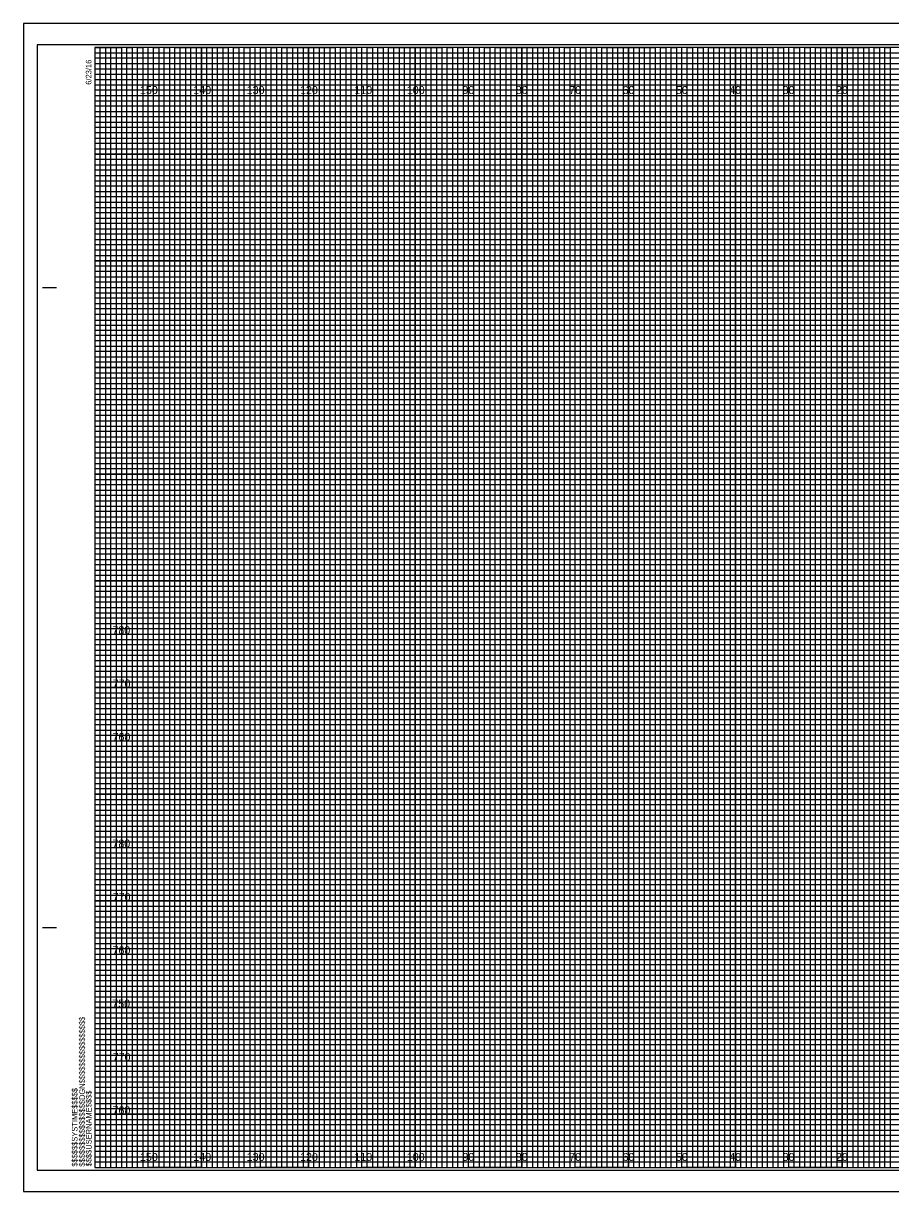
# Model space of a CAD drawing. Extents: x -13 to 323, y -4 to 214.
# Drawn here: x -13.4 to 149.1, y -4.5 to 214.5 of the extents above; entities that cross this region are included whole.
import ezdxf

# ---------------------------------------------------------------- set-up
doc = ezdxf.new("R2010")
doc.units = 0
for name, color, linetype in [('Exist Cross Section Cell', 7, 'Continuous'), ('Exist XS Center Line Elevation Label', 7, 'Continuous'), ('Exist XS Ground Line', 7, 'Continuous'), ('Prop CMT Pvmt Course 2', 7, 'Continuous'), ('Prop CMT Pvmt Course 3', 7, 'Continuous'), ('Prop CMT Pvmt Surface', 7, 'Continuous'), ('Prop CMT Shld Paved Course 1', 7, 'Continuous'), ('Prop CMT Shld Paved Course 3', 7, 'Continuous'), ('Prop CMT Subgrade Earthwork', 7, 'Continuous'), ('Scratch_Level_1', 7, 'Continuous'), ('Scratch_Level_7', 7, 'Continuous')]:
    doc.layers.add(name, color=color, linetype=linetype)

msp = doc.modelspace()

# ---------------------------------------------------------------- linework, layer by layer
at = {"layer": 'Exist XS Center Line Elevation Label'}
for points in [[(0, 210), (5, 210), (5, 0), (15, 0), (15, 210), (25, 210), (25, 0), (35, 0), (35, 210), (45, 210), (45, 0), (55, 0), (55, 210), (65, 210), (65, 0), (75, 0), (75, 210), (85, 210), (85, 0), (95, 0), (95, 210), (105, 210), (105, 0), (115, 0), (115, 210), (125, 210), (125, 0), (135, 0), (135, 210), (145, 210), (145, 0), (155, 0)], [(0, 205), (275, 205)], [(0, 185), (320, 185), (320, 195), (0, 195)], [(0, 165), (320, 165), (320, 175), (0, 175)], [(0, 145), (320, 145), (320, 155), (0, 155)], [(0, 125), (320, 125), (320, 135), (0, 135)], [(0, 105), (320, 105), (320, 115), (0, 115)], [(0, 85), (320, 85), (320, 95), (0, 95)], [(0, 65), (320, 65), (320, 75), (0, 75)], [(0, 45), (320, 45), (320, 55), (0, 55)], [(0, 25), (320, 25), (320, 35), (0, 35)], [(0, 5), (320, 5), (320, 15), (0, 15)]]:
    msp.add_lwpolyline(points, dxfattribs=at)
at = {"layer": 'Exist XS Ground Line'}
for p, q in [((10, 210), (0, 210)), ((10, 0), (10, 210)), ((30, 210), (20, 210)), ((20, 210), (20, 0)), ((30, 0), (30, 210)), ((50, 210), (40, 210)), ((40, 210), (40, 0)), ((50, 0), (50, 210)), ((70, 210), (60, 210)), ((60, 210), (60, 0)), ((70, 0), (70, 210)), ((90, 210), (80, 210)), ((80, 210), (80, 0)), ((90, 0), (90, 210)), ((110, 210), (100, 210)), ((100, 210), (100, 0)), ((110, 0), (110, 210)), ((130, 210), (120, 210)), ((120, 210), (120, 0)), ((130, 0), (130, 210)), ((150, 210), (140, 210)), ((140, 210), (140, 0)), ((20, 0), (10, 0)), ((40, 0), (30, 0)), ((60, 0), (50, 0)), ((80, 0), (70, 0)), ((100, 0), (90, 0)), ((120, 0), (110, 0)), ((140, 0), (130, 0))]:
    msp.add_line(p, q, dxfattribs=at)
for points in [[(0, 200), (320, 200), (320, 190), (0, 190)], [(0, 180), (320, 180), (320, 170), (0, 170)], [(0, 160), (320, 160), (320, 150), (0, 150)], [(0, 140), (320, 140), (320, 130), (0, 130)], [(0, 120), (320, 120), (320, 110), (0, 110)], [(0, 100), (320, 100), (320, 90), (0, 90)], [(0, 80), (320, 80), (320, 70), (0, 70)], [(0, 60), (320, 60), (320, 50), (0, 50)], [(0, 40), (320, 40), (320, 30), (0, 30)], [(0, 20), (320, 20), (320, 10), (0, 10)]]:
    msp.add_lwpolyline(points, dxfattribs=at)
at = {"layer": 'Prop CMT Pvmt Course 2'}
msp.add_lwpolyline([(-10.8, -0.5), (322.4, -0.5), (322.4, 210.5), (-10.8, 210.5)], close=True, dxfattribs=at)
at = {"layer": 'Prop CMT Pvmt Course 3'}
for p, q in [((10, 0), (10, 210)), ((20, 0), (20, 210)), ((30, 0), (30, 210)), ((40, 0), (40, 210)), ((50, 0), (50, 210)), ((60, 0), (60, 210)), ((70, 0), (70, 210)), ((80, 0), (80, 210)), ((90, 0), (90, 210)), ((100, 0), (100, 210)), ((110, 0), (110, 210)), ((120, 0), (120, 210)), ((130, 0), (130, 210)), ((140, 0), (140, 210)), ((0, 200), (320, 200)), ((0, 190), (320, 190)), ((0, 180), (320, 180)), ((0, 170), (320, 170)), ((0, 160), (320, 160)), ((0, 150), (320, 150)), ((0, 140), (320, 140)), ((0, 130), (320, 130)), ((0, 120), (320, 120)), ((0, 110), (320, 110)), ((0, 100), (320, 100)), ((0, 90), (320, 90)), ((0, 80), (320, 80)), ((0, 70), (320, 70)), ((0, 60), (320, 60)), ((0, 50), (320, 50)), ((0, 40), (320, 40)), ((0, 30), (320, 30)), ((0, 20), (320, 20)), ((0, 10), (320, 10))]:
    msp.add_line(p, q, dxfattribs=at)
at = {"layer": 'Prop CMT Shld Paved Course 1'}
for points in [[(0, 0), (1, 0), (1, 210), (2, 210), (2, 0)], [(2, 0), (3, 0), (3, 210), (4, 210), (4, 0)], [(5, 0), (6, 0), (6, 210), (7, 210), (7, 0)], [(7, 0), (8, 0), (8, 210), (9, 210), (9, 0)], [(10, 0), (11, 0), (11, 210), (12, 210), (12, 0)], [(12, 0), (13, 0), (13, 210), (14, 210), (14, 0)], [(15, 0), (16, 0), (16, 210), (17, 210), (17, 0)], [(17, 0), (18, 0), (18, 210), (19, 210), (19, 0)], [(20, 0), (21, 0), (21, 210), (22, 210), (22, 0)], [(22, 0), (23, 0), (23, 210), (24, 210), (24, 0)], [(25, 0), (26, 0), (26, 210), (27, 210), (27, 0)], [(27, 0), (28, 0), (28, 210), (29, 210), (29, 0)], [(30, 0), (31, 0), (31, 210), (32, 210), (32, 0)], [(32, 0), (33, 0), (33, 210), (34, 210), (34, 0)], [(35, 0), (36, 0), (36, 210), (37, 210), (37, 0)], [(37, 0), (38, 0), (38, 210), (39, 210), (39, 0)], [(40, 0), (41, 0), (41, 210), (42, 210), (42, 0)], [(42, 0), (43, 0), (43, 210), (44, 210), (44, 0)], [(45, 0), (46, 0), (46, 210), (47, 210), (47, 0)], [(47, 0), (48, 0), (48, 210), (49, 210), (49, 0)], [(50, 0), (51, 0), (51, 210), (52, 210), (52, 0)], [(52, 0), (53, 0), (53, 210), (54, 210), (54, 0)], [(55, 0), (56, 0), (56, 210), (57, 210), (57, 0)], [(57, 0), (58, 0), (58, 210), (59, 210), (59, 0)], [(60, 0), (61, 0), (61, 210), (62, 210), (62, 0)], [(62, 0), (63, 0), (63, 210), (64, 210), (64, 0)], [(65, 0), (66, 0), (66, 210), (67, 210), (67, 0)], [(67, 0), (68, 0), (68, 210), (69, 210), (69, 0)], [(70, 0), (71, 0), (71, 210), (72, 210), (72, 0)], [(72, 0), (73, 0), (73, 210), (74, 210), (74, 0)], [(75, 0), (76, 0), (76, 210), (77, 210), (77, 0)], [(77, 0), (78, 0), (78, 210), (79, 210), (79, 0)], [(80, 0), (81, 0), (81, 210), (82, 210), (82, 0)], [(82, 0), (83, 0), (83, 210), (84, 210), (84, 0)], [(85, 0), (86, 0), (86, 210), (87, 210), (87, 0)], [(87, 0), (88, 0), (88, 210), (89, 210), (89, 0)], [(90, 0), (91, 0), (91, 210), (92, 210), (92, 0)], [(92, 0), (93, 0), (93, 210), (94, 210), (94, 0)], [(95, 0), (96, 0), (96, 210), (97, 210), (97, 0)], [(97, 0), (98, 0), (98, 210), (99, 210), (99, 0)], [(100, 0), (101, 0), (101, 210), (102, 210), (102, 0)], [(102, 0), (103, 0), (103, 210), (104, 210), (104, 0)], [(105, 0), (106, 0), (106, 210), (107, 210), (107, 0)], [(107, 0), (108, 0), (108, 210), (109, 210), (109, 0)], [(110, 0), (111, 0), (111, 210), (112, 210), (112, 0)], [(112, 0), (113, 0), (113, 210), (114, 210), (114, 0)], [(115, 0), (116, 0), (116, 210), (117, 210), (117, 0)], [(117, 0), (118, 0), (118, 210), (119, 210), (119, 0)], [(120, 0), (121, 0), (121, 210), (122, 210), (122, 0)], [(122, 0), (123, 0), (123, 210), (124, 210), (124, 0)], [(125, 0), (126, 0), (126, 210), (127, 210), (127, 0)], [(127, 0), (128, 0), (128, 210), (129, 210), (129, 0)], [(130, 0), (131, 0), (131, 210), (132, 210), (132, 0)], [(132, 0), (133, 0), (133, 210), (134, 210), (134, 0)], [(135, 0), (136, 0), (136, 210), (137, 210), (137, 0)], [(137, 0), (138, 0), (138, 210), (139, 210), (139, 0)], [(140, 0), (141, 0), (141, 210), (142, 210), (142, 0)], [(142, 0), (143, 0), (143, 210), (144, 210), (144, 0)], [(145, 0), (146, 0), (146, 210), (147, 210), (147, 0)], [(147, 0), (148, 0), (148, 210), (149, 210), (149, 0)]]:
    msp.add_lwpolyline(points, dxfattribs=at)
at = {"layer": 'Prop CMT Shld Paved Course 3'}
msp.add_lwpolyline([(-13.4, -4.5), (323.3, -4.5), (323.3, 214.5), (-13.4, 214.5)], close=True, dxfattribs=at)
at = {"layer": 'Prop CMT Subgrade Earthwork'}
for p, q in [((323.3, 214.5), (-13.4, 214.5)), ((-13.4, 214.5), (-13.4, -4.5)), ((-13.4, -4.5), (323.3, -4.5))]:
    msp.add_line(p, q, dxfattribs=at)
at = {"layer": 'Scratch_Level_1'}
for p, q in [((0, 209), (260, 209)), ((260, 207.98), (0, 207.98)), ((0, 207.98), (0, 207)), ((0, 207), (260, 207)), ((260, 205.89), (0, 205.89)), ((0, 205.89), (0, 204)), ((0, 204), (320, 204))]:
    msp.add_line(p, q, dxfattribs=at)
for points in [[(0, 203), (270, 203), (320, 203), (320, 202), (0, 202)], [(0, 201), (320, 201), (320, 199), (0, 199)], [(0, 198), (320, 198), (320, 197), (0, 196.98)], [(0, 196), (320, 196), (320, 194), (0, 194)], [(0, 193), (320, 193), (320, 192), (0, 192)], [(0, 191), (320, 191), (320, 189), (0, 189)], [(0, 188), (320, 188), (320, 187), (0, 187)], [(0, 186), (320, 186), (320, 184), (0, 184)], [(0, 183), (320, 183), (320, 182), (0, 182)], [(0, 181), (320, 181), (320, 179), (0, 179)], [(0, 178), (320, 178), (320, 177), (0, 177)], [(0, 176), (320, 176), (320, 173.95), (320, 173), (320, 172), (0, 172)], [(0, 174), (320, 174), (320, 173), (0, 173)], [(0, 171), (320, 171), (320, 169), (0, 169.03)], [(0, 169.03), (320, 169), (320, 168), (0, 168)], [(0, 167), (320, 167), (320, 166), (0, 166)], [(0, 164), (320, 164), (320, 163), (0, 163)], [(0, 162), (320, 162), (320, 161), (0, 161)], [(-0.07, 158.89), (320, 158.89), (320, 157.88), (-0.07, 157.88)], [(0, 157), (320, 157), (320, 156), (0, 156)], [(0, 154), (320, 154), (320, 153), (0, 153)], [(0, 152), (320, 152), (320, 151), (0, 151)], [(0, 149), (320, 149), (320, 148), (0, 148)], [(0, 147), (320, 147), (320, 146), (0, 146)], [(0, 144), (320, 144), (320, 143), (0, 143)], [(0, 142), (320, 142), (320, 141), (0, 141)], [(0, 139), (320, 139), (319.99, 137.98), (0, 138)], [(0, 137), (320, 137), (320, 136), (0, 136)], [(0, 134), (320, 134), (320, 133), (0, 133)], [(0, 132), (320, 132), (320, 131), (0, 131)], [(0, 129), (320, 129), (320, 128), (0, 128)], [(0, 127), (320, 127), (320, 126), (0, 126)], [(0, 124), (320, 124), (320, 123), (0, 123)], [(0, 122), (320, 122), (320, 121), (0, 121)], [(0, 119), (320, 119), (320, 118), (0, 118)], [(0, 116.99), (320.07, 116.91), (320, 116), (0, 116)], [(0, 114), (320, 114), (320, 113), (0, 113)], [(0, 112), (320, 112), (320, 111), (0, 111)], [(0, 109), (320, 109), (320, 108), (0, 108)], [(0, 107), (320, 107), (320, 106), (0, 106)], [(0, 104), (320, 104), (320, 103), (0, 103)], [(0, 102), (320, 102), (320, 101), (0, 101)], [(0, 99), (320, 99), (320, 98), (0, 98)], [(0, 97), (320, 97), (320, 96), (0, 96)], [(0, 94), (320, 94), (320, 93), (0, 93)], [(0, 92), (320, 92), (320, 91), (0, 91)], [(0, 89), (320, 89), (320, 88), (0, 88)], [(0, 87), (320, 87), (320, 86), (0, 86)], [(0, 84), (320, 84), (320, 83), (0, 83)], [(0, 82), (320, 82), (320, 81), (0, 81)], [(0, 79), (320, 79), (319.99, 77.98), (0, 78)], [(0, 77), (320, 77), (320, 76), (0, 76)], [(0, 74), (320, 74), (320, 73), (0, 73)], [(0, 72), (320, 72), (320, 71), (0, 71)], [(0, 69), (320, 69), (320, 68), (0, 68)], [(0, 67), (320, 67), (320, 66), (0, 66)], [(0, 64), (320, 64), (320, 63), (0, 63)], [(0, 62), (320, 62), (320, 61), (0, 61)], [(0, 59), (320, 59), (320, 58), (0, 58)], [(0, 56.99), (320.07, 56.91), (320, 56), (0, 56)], [(0, 54), (320, 54), (320, 53), (0, 53)], [(0, 52), (320, 52), (320, 51), (0, 51)], [(0, 49), (320, 49), (320, 48), (0, 48)], [(0, 47), (320, 47), (320, 46), (0, 46)], [(0, 44), (320, 44), (320, 43), (0, 43)], [(0, 42), (320, 42), (320, 41), (0, 41)], [(0, 39), (320, 39), (320, 38), (0, 38)], [(0, 37), (320, 37), (320, 36), (0, 36)], [(0, 34), (320, 34), (320, 33), (0, 33)], [(0, 32), (320, 32), (320, 31), (0, 31)], [(0, 29), (320, 29), (320, 28), (0, 28)], [(0, 27), (320, 27), (320, 26), (0, 26)], [(0, 24), (320, 24), (320, 23), (0, 23)], [(0, 22), (320, 22), (320, 21), (0, 21)], [(0, 19), (320, 19), (320, 18), (0, 18)], [(0, 17), (320, 17), (320, 16), (0, 16)], [(0, 14), (320, 14), (320, 13), (0, 13)], [(0, 12), (320, 12), (320, 11), (0, 11)], [(0, 9), (320, 9), (320, 8), (0, 8)], [(0, 7), (320, 7), (320, 6), (0, 6)], [(0, 4), (320, 4), (320, 3), (0, 3)], [(0, 2), (320, 2), (320, 1), (0, 1)]]:
    msp.add_lwpolyline(points, dxfattribs=at)
at = {"layer": 'Scratch_Level_7'}
for p, q in [((-9.8, 165), (-7.3, 165)), ((-9.7, 165), (-7.2, 165)), ((-9.8, 45), (-7.3, 45)), ((-9.7, 45), (-7.2, 45)), ((0, 0), (0, 0)), ((0, 0), (0, 0)), ((0, 0), (0, 0)), ((0, 0), (0, 0)), ((0, 0), (0, 0)), ((0, 0), (0, 0)), ((0, 0), (0, 0))]:
    msp.add_line(p, q, dxfattribs=at)
msp.add_lwpolyline([(320, 210), (0, 210), (0, 0), (320, 0)], close=True, dxfattribs=at)

# ---------------------------------------------------------------- texts
at = {"layer": 'Exist Cross Section Cell'}
for s, p in [('150', (8.44, 201.25)), ('140', (18.44, 201.25)), ('130', (28.44, 201.25)), ('120', (38.44, 201.25)), ('110', (48.62, 201.25)), ('100', (58.44, 201.25)), ('90', (68.86, 201.25)), ('80', (78.86, 201.25)), ('70', (88.86, 201.25)), ('60', (98.86, 201.25)), ('50', (108.86, 201.25)), ('40', (118.86, 201.25)), ('30', (128.86, 201.25)), ('20', (138.86, 201.25)), ('150', (8.44, 1.25)), ('140', (18.44, 1.25)), ('130', (28.44, 1.25)), ('120', (38.44, 1.25)), ('110', (48.62, 1.25)), ('100', (58.44, 1.25)), ('90', (68.86, 1.25)), ('80', (78.86, 1.25)), ('70', (88.86, 1.25)), ('60', (98.86, 1.25)), ('50', (108.86, 1.25)), ('40', (118.86, 1.25)), ('30', (128.86, 1.25)), ('20', (138.86, 1.25))]:
    msp.add_text(s, height=1.5, dxfattribs=at).set_placement(p)
at = {"layer": 'Prop CMT Pvmt Surface'}
for s, p in [('780', (3.28, 100)), ('770', (3.33, 90)), ('760', (3.3, 80)), ('780', (3.28, 60)), ('770', (3.33, 50)), ('760', (3.3, 40)), ('750', (3.25, 30)), ('770', (3.33, 20)), ('760', (3.3, 10))]:
    msp.add_text(s, height=1.5, dxfattribs=at).set_placement(p)
at = {"layer": 'Scratch_Level_7'}
for s, p in [('6/23/16', (-0.65, 203)), ('$$$$$$$$$$$$$$$$DGN$$$$$$$$$$$$$$$$', (-1.88, 0.18)), ('$$$$$$SYSTIME$$$$$', (-3.26, 0.18)), ('$$$$USERNAME$$$$', (-0.62, 0.23))]:
    msp.add_text(s, height=1.05, rotation=90, dxfattribs=at).set_placement(p)

doc.saveas('drawing.dxf')
